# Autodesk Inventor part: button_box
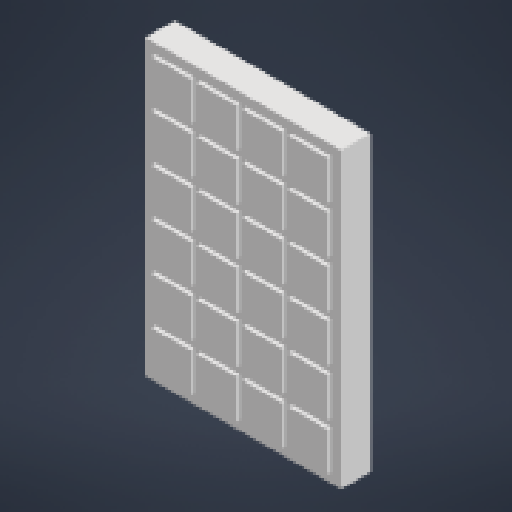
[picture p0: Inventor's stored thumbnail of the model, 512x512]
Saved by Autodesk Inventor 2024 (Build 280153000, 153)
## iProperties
Created: 2023-09
Part Number: button_box
Material: Generic
Document SubType Name: Modeling
Designer: mammothbane
Density: 1 g/cm^3
Appearance: Default
Author: mammothbane
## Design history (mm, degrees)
sketch "Sketch1"
  geometry: L1 (-50, 75)-(50, 75); L2 (50, 75)-(50, -75); L3 (50, -75)-(-50, -75); L4 (-50, -75)-(-50, 75); L5 (-50, 75)-(50, -75); L6 (50, 75)-(-50, -75); 1 further point
  constraints: 12 end point, 2 midpoint, 2 parallel, 1 horizontal, 1 perpendicular
  dimensions: "width" = 100 distance of L2.end L3.end; "length" = 150 distance of L1.end L2.end
extrude "Extrusion1" new body sketch "Sketch1" taper "d3" = 0 deg; distance "thickness" = 15
sketch "Sketch2"
  geometry: L1 (45, 70)-(25, 70); L2 (25, 70)-(25, 50); L3 (25, 50)-(45, 50); L4 (45, 50)-(45, 70); L5 (45, 70)-(25, 50); L6 (25, 70)-(45, 50); L7 (50, -75)-(50, 75) reference; L8 (50, 75)-(-50, 75) reference; 3 further points
  constraints: 12 end point, 3 midpoint, 2 parallel, 1 horizontal, 1 perpendicular
  dimensions: "button_width" = 20 distance of L2.end L3.end; "button_height" = 20 distance of L3.end L1.start (= button_width); "d8" = 5 distance from line of L7 point (45, 60) (= buf_width); "d9" = 5 distance between parallel lines of L8 L1 (= buf_length)
extrude "Extrusion2" join sketch "Sketch2" distance "d6" = 2; taper "d7" = 0 deg
body "Solid1"
pattern_linear "Rectangular Pattern1" dims "d12" = 23.33333 (= button_spacing_width), "d15" = 24 (= button_spacing_height)
other parameters: "buf_width" = 5 [user parameter; used in 2 equation terms], "buf_length" = 5 [user parameter; used in 2 equation terms], "button_spacing_width" = 23.33333 (computed from button_width, button_extent_width, ncol) [user parameter; used in 1 equation term], "button_spacing_height" = 24 (computed from button_height, button_extent_length, nrow) [user parameter; used in 1 equation term]
